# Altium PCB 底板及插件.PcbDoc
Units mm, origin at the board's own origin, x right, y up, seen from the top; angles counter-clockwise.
Board outline 152.4 x 101.6 mm, 2 copper layers (Top Layer, Bottom Layer); 2 components, 31 nets, 12 pads, 0 vias.
Unrouted connection lines stored in the file: 2.
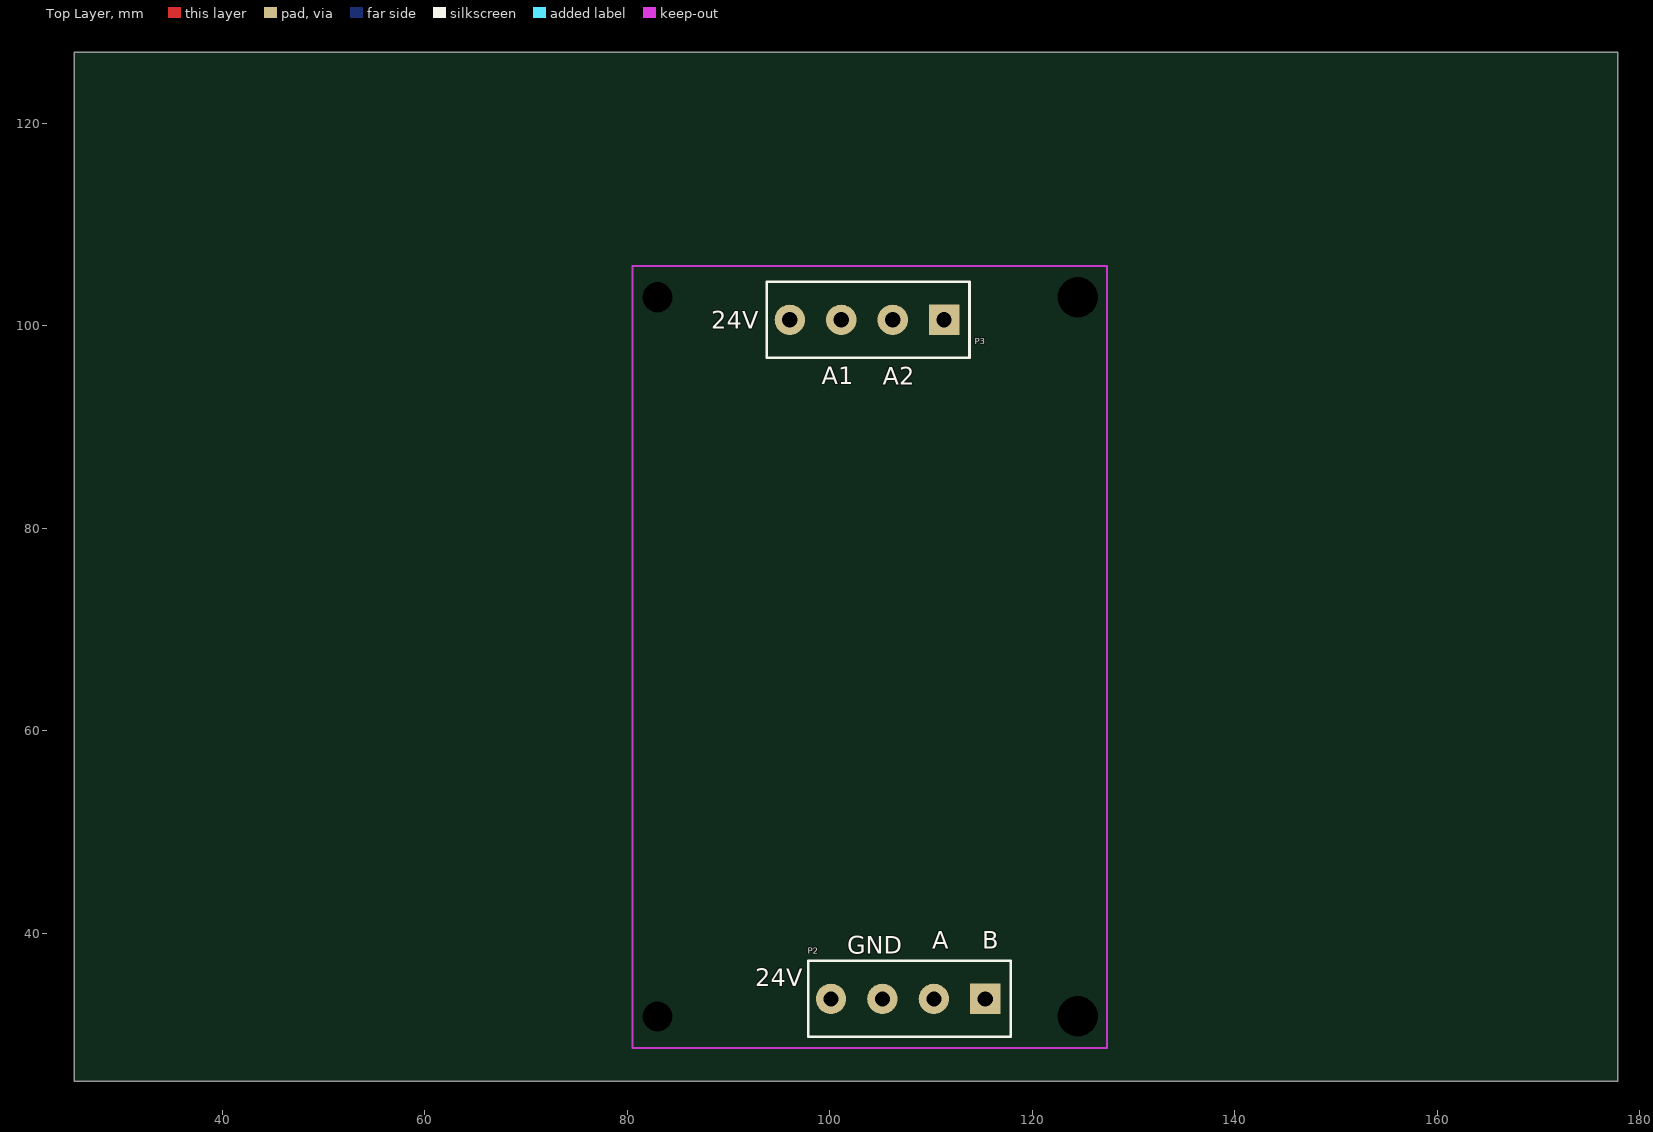
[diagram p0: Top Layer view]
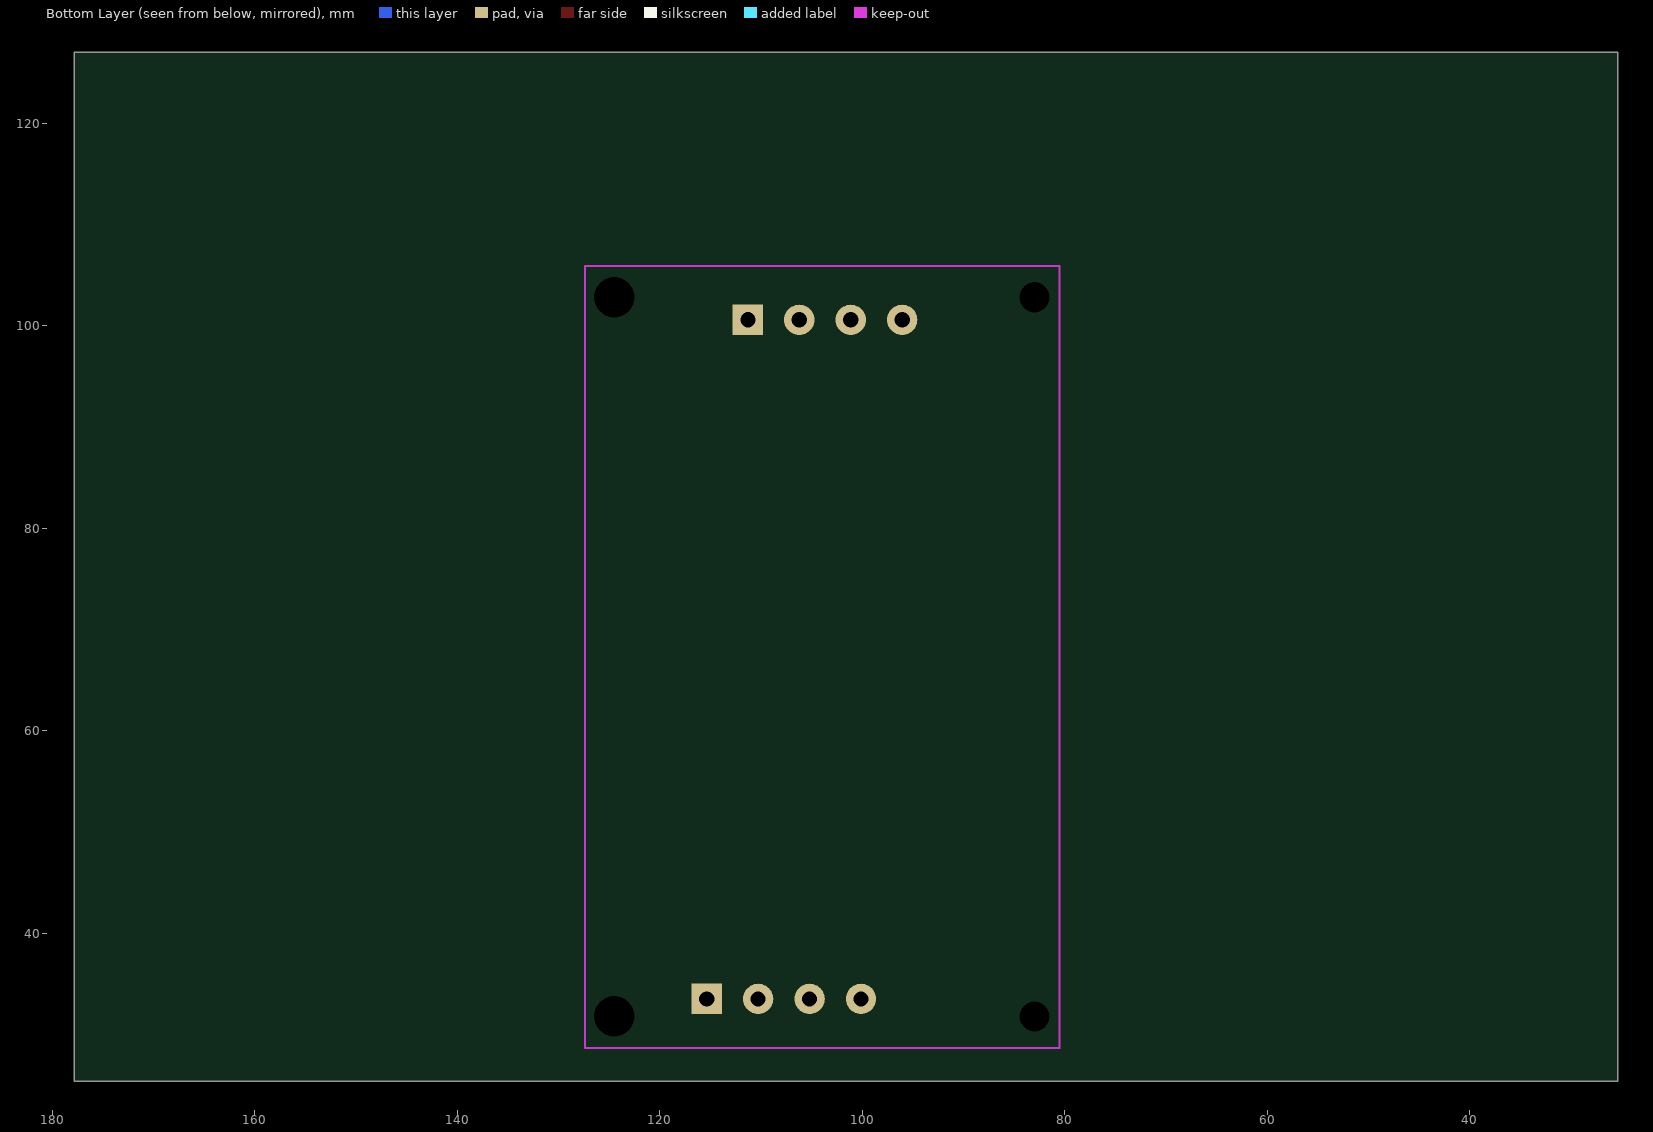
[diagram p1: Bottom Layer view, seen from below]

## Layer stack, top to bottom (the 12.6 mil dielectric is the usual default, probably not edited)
Top Solder: solder mask 0.0102, Solder Resist, Dk 3.5
Top Layer: signal copper 0.0356
Dielectric1: dielectric 0.32, FR-4, Dk 4.8
Bottom Layer: signal copper 0.0356
Bottom Solder: solder mask 0.0102, Solder Resist, Dk 3.5

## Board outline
25.4,25.4 177.8,25.4 177.8,127 25.4,127

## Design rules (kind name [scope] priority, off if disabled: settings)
Clearance [All] p1: gap=0.154 ignorepadtopadclearanceinfootprint=FALSE except(0: Arc-Hole Track-Hole SMDPad-Hole THPad-Hole Via-Hole Fill-Hole Poly-Hole Region-Hole Text-Hole)
FabricationTestPointUsage TestPointUsage [All] p1: valid=0 allowmultiple=FALSE
FabricationTestpoint Testpoint [All] p1: side=3 testpointundercomponent=TRUE minsize=1.016 maxsize=2.54 preferedsize=1.524 minholesize=0 maxholesize=1.016 preferedholesize=0.813 testpointgrid=0.025 allowsidetop=TRUE allowsidebottom=TRUE usegrid=TRUE gridtolerance=0
PolygonConnect [All] p1: connectstyle=Relief reliefconductorwidth=0.254 reliefentries=4 polygonreliefangle="90 Angle" airgapwidth=0.254
RoutingVias [All] p1: holewidth=0.411 width=0.6 viastyle="Through Hole" minholewidth=0.3 minwidth=0.5 maxholewidth=0.711 maxwidth=1
SolderMaskExpansion [All] p1: expansion=0.102
Width [All] p1: maxlimit=1.254 minlimit=0.154 preferedwidth=0.254
28 further rules are at their usual default settings.

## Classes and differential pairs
component class 12AD0-10: P3

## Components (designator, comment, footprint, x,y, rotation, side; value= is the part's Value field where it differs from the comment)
P2 "Header 4H" 5.08dip-4 117.856,33.528 r180 top
P3 "Header 4" 5.08dip-4 113.792,100.584 r180 top

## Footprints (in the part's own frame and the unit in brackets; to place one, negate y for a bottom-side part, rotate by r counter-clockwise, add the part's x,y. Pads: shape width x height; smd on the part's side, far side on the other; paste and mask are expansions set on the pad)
5.08dip-4 [mm]
  rect 3x3 hole 1.5: 1(2.5,0)
  round 3 hole 1.5: 2(7.58,0) 3(12.66,0) 4(17.74,0)
  silkscreen extent 0,-3.75 20,3.75

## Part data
P2: "Header, 4-Pin, Right Angle"
P3: "Header, 4-Pin"

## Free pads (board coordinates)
  round 0.7 hole 3: 0(82.982,102.794) 2(82.982,31.794)
  round 0.7 hole 4: 1(124.5,102.794) 3(124.5,31.794)

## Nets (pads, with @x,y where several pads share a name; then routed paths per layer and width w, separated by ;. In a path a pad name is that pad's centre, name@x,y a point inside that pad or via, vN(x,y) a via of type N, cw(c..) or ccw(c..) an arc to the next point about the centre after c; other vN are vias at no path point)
3V3: 
5V: 
24V: 
485DIR: 
A: P2.2
A1+: P3.3
A1_ADC: 
A2+: P3.2
A2_ADC: 
A3_ADC: 
B: P2.1
BOOT0: 
BOOT1: 
GND: P2.3 P3.1
I2C_SCL: 
I2C_SDA: 
LED: 
M485R: 
M485T: 
NetC8_2: 
NetC10_2: 
NetC11_2: 
NetD2_A: 
NetD3_A: 
NetD6_A: 
NetD7_A: 
NetR2_2: 
NetR3_2: 
PWI: P2.4 P3.4
SWCLK: 
SWDIO: 

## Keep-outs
Keep-Out Layer:
  lines w0.203: 80.518,28.702 127.381,28.702 127.381,105.918 80.518,105.918 80.518,28.702

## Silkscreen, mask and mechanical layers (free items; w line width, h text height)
Top Overlay:
  text "24V" at 88.29,99.72 h1.72
  text "A1" at 99.187,94.234 h1.72
  text "A2" at 105.207,94.183 h1.72
  text "A" at 110.109,38.481 h1.72
  text "B" at 115.037,38.481 h1.72
  text "GND" at 101.727,37.973 h1.72
  text "24V" at 92.659,34.798 h1.72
